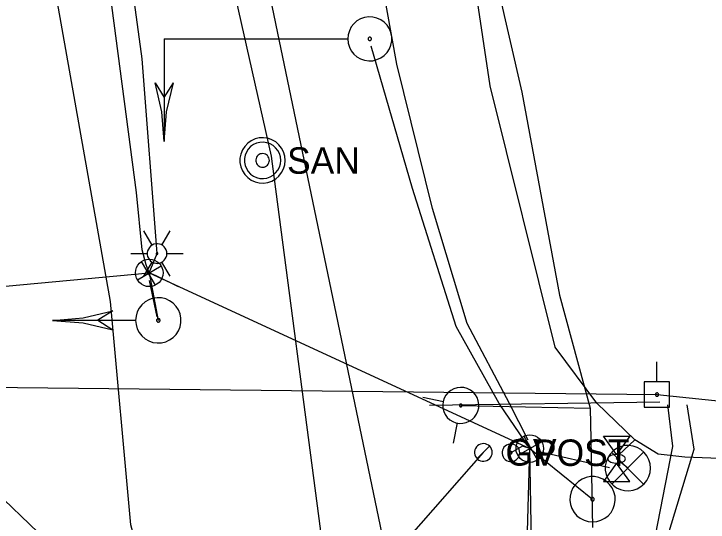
# Model space of a CAD drawing. Extents: x 600849 to 606371, y 330010 to 403088.
# Drawn here: x 605030.2 to 605131.2, y 338029.9 to 338103.8 of the extents above; entities that cross this region are included whole.
import ezdxf

# ---------------------------------------------------------------- set-up
doc = ezdxf.new("R2010")
doc.units = 0
for name, color, linetype in [('E_LTG', 7, 'Continuous'), ('E_LTG_CID', 7, 'Continuous'), ('E_MISCPROP', 7, 'Continuous'), ('E_SIG', 7, 'Continuous'), ('E_SIG_Conduit', 7, 'Continuous'), ('E_UTL_AG', 7, 'Continuous'), ('E_UTL_E_UG', 7, 'Continuous'), ('E_UTL_EPowerPole', 7, 'Continuous'), ('E_UTL_FO_UG', 7, 'Continuous'), ('E_UTL_G', 7, 'Continuous'), ('E_UTL_G_UG', 7, 'Continuous'), ('E_UTL_Loop_UG', 7, 'Continuous'), ('E_UTL_Overhead', 7, 'Continuous'), ('E_UTL_SAN', 7, 'Continuous'), ('E_UTL_SAN_UG', 7, 'Continuous'), ('E_UTL_TV_UG', 7, 'Continuous'), ('E_UTL_W_UG', 7, 'Continuous'), ('E_UTL_WHydrant', 7, 'Continuous')]:
    doc.layers.add(name, color=color, linetype=linetype)

# ---------------------------------------------------------------- blocks, each defined once
blk = doc.blocks.new('_U321')
at = {"layer": 'E_SIG'}
for p, q in [((0, 6.1), (0, -6.1)), ((-6.09, 0.4), (6.1, 0.4))]:
    blk.add_line(p, q, dxfattribs=at)
blk.add_circle((0, 0.01), 6.1, dxfattribs=at)
blk = doc.blocks.new('_U322')
at = {"layer": 'E_SIG'}
for p, q in [((0, 6.1), (0, -6.1)), ((-6.09, 0.4), (6.1, 0.4))]:
    blk.add_line(p, q, dxfattribs=at)
blk.add_circle((0, 0.01), 6.1, dxfattribs=at)

msp = doc.modelspace()

# ---------------------------------------------------------------- linework, layer by layer
at = {"layer": 'E_LTG'}
for points in [[(605050.29, 338070.16), (605049.09, 338072.22)], [(605051.71, 338070.16), (605052.91, 338072.22)], [(605052.43, 338068.92), (605052.4, 338069.19), (605052.33, 338069.45), (605052.2, 338069.7), (605052.03, 338069.91), (605051.83, 338070.09), (605051.59, 338070.22), (605051.34, 338070.31), (605051.07, 338070.35), (605050.8, 338070.34), (605050.53, 338070.27), (605050.29, 338070.16), (605050.06, 338070), (605049.88, 338069.81), (605049.73, 338069.58), (605049.63, 338069.33), (605049.58, 338069.06), (605049.58, 338068.79), (605049.63, 338068.52), (605049.73, 338068.27), (605049.88, 338068.04), (605050.06, 338067.84), (605050.29, 338067.69), (605050.53, 338067.57), (605050.8, 338067.51), (605051.07, 338067.5), (605051.34, 338067.54), (605051.59, 338067.62), (605051.83, 338067.76), (605052.03, 338067.94), (605052.2, 338068.15), (605052.33, 338068.39), (605052.4, 338068.65), (605052.43, 338068.92)], [(605052.43, 338068.92), (605052.4, 338069.19), (605052.33, 338069.45), (605052.2, 338069.7), (605052.03, 338069.91), (605051.83, 338070.09), (605051.59, 338070.22), (605051.34, 338070.31), (605051.07, 338070.35), (605050.8, 338070.34), (605050.53, 338070.27), (605050.29, 338070.16), (605050.06, 338070), (605049.88, 338069.81), (605049.73, 338069.58), (605049.63, 338069.33), (605049.58, 338069.06), (605049.58, 338068.79), (605049.63, 338068.52), (605049.73, 338068.27), (605049.88, 338068.04), (605050.06, 338067.84), (605050.29, 338067.69), (605050.53, 338067.57), (605050.8, 338067.51), (605051.07, 338067.5), (605051.34, 338067.54), (605051.59, 338067.62), (605051.83, 338067.76), (605052.03, 338067.94), (605052.2, 338068.15), (605052.33, 338068.39), (605052.4, 338068.65), (605052.43, 338068.92)], [(605052.43, 338068.92), (605052.4, 338069.19), (605052.33, 338069.45), (605052.2, 338069.7), (605052.03, 338069.91), (605051.83, 338070.09), (605051.59, 338070.22), (605051.34, 338070.31), (605051.07, 338070.35), (605050.8, 338070.34), (605050.53, 338070.27), (605050.29, 338070.16), (605050.06, 338070), (605049.88, 338069.81), (605049.73, 338069.58), (605049.63, 338069.33), (605049.58, 338069.06), (605049.58, 338068.79), (605049.63, 338068.52), (605049.73, 338068.27), (605049.88, 338068.04), (605050.06, 338067.84), (605050.29, 338067.69), (605050.53, 338067.57), (605050.8, 338067.51), (605051.07, 338067.5), (605051.34, 338067.54), (605051.59, 338067.62), (605051.83, 338067.76), (605052.03, 338067.94), (605052.2, 338068.15), (605052.33, 338068.39), (605052.4, 338068.65), (605052.43, 338068.92)], [(605047.19, 338068.92), (605049.57, 338068.92)], [(605051.12, 338068.92), (605051.12, 338068.95), (605051.11, 338068.97), (605051.1, 338068.99), (605051.09, 338069.01), (605051.07, 338069.02), (605051.05, 338069.03), (605051.03, 338069.04), (605051.01, 338069.04), (605050.98, 338069.04), (605050.96, 338069.04), (605050.94, 338069.03), (605050.92, 338069.01), (605050.91, 338069), (605050.89, 338068.98), (605050.89, 338068.96), (605050.88, 338068.94), (605050.88, 338068.91), (605050.89, 338068.89), (605050.89, 338068.87), (605050.91, 338068.85), (605050.92, 338068.83), (605050.94, 338068.82), (605050.96, 338068.81), (605050.98, 338068.81), (605051.01, 338068.8), (605051.03, 338068.81), (605051.05, 338068.82), (605051.07, 338068.83), (605051.09, 338068.84), (605051.1, 338068.86), (605051.11, 338068.88), (605051.12, 338068.9), (605051.12, 338068.92)], [(605052.43, 338068.92), (605054.81, 338068.92)], [(605049.09, 338065.62), (605050.29, 338067.69)], [(605052.91, 338065.62), (605051.71, 338067.69)]]:
    msp.add_lwpolyline(points, dxfattribs=at)
at = {"layer": 'E_LTG_CID'}
for points in [[(605051, 338068.92), (605048.82, 338097.26), (605044.44, 338129.66), (605035.18, 338175.44)], [(605049.87, 338066.12), (605051, 338068.92)]]:
    msp.add_lwpolyline(points, dxfattribs=at)
at = {"layer": 'E_MISCPROP'}
for points in [[(605103.75, 338039.96), (605103.73, 338040.21), (605103.66, 338040.44), (605103.55, 338040.66), (605103.4, 338040.85), (605103.21, 338041.01), (605103, 338041.13), (605102.77, 338041.21), (605102.53, 338041.25), (605102.29, 338041.23), (605102.05, 338041.18), (605101.83, 338041.08), (605101.63, 338040.93), (605101.46, 338040.76), (605101.33, 338040.55), (605101.24, 338040.33), (605101.19, 338040.09), (605101.19, 338039.84), (605101.24, 338039.6), (605101.33, 338039.38), (605101.46, 338039.17), (605101.63, 338038.99), (605101.83, 338038.85), (605102.05, 338038.75), (605102.29, 338038.69), (605102.53, 338038.68), (605102.77, 338038.72), (605103, 338038.8), (605103.21, 338038.92), (605103.4, 338039.08), (605103.55, 338039.27), (605103.66, 338039.49), (605103.73, 338039.72), (605103.75, 338039.96)], [(605102.63, 338039.96), (605102.63, 338039.99), (605102.62, 338040.02), (605102.6, 338040.05), (605102.59, 338040.07), (605102.56, 338040.09), (605102.54, 338040.11), (605102.51, 338040.12), (605102.48, 338040.12), (605102.45, 338040.12), (605102.42, 338040.12), (605102.39, 338040.1), (605102.36, 338040.09), (605102.34, 338040.06), (605102.33, 338040.04), (605102.32, 338040.01), (605102.31, 338039.98), (605102.31, 338039.95), (605102.32, 338039.92), (605102.33, 338039.89), (605102.34, 338039.86), (605102.36, 338039.84), (605102.39, 338039.82), (605102.42, 338039.81), (605102.45, 338039.81), (605102.48, 338039.8), (605102.51, 338039.81), (605102.54, 338039.82), (605102.56, 338039.83), (605102.59, 338039.85), (605102.6, 338039.88), (605102.62, 338039.9), (605102.63, 338039.93), (605102.63, 338039.96)]]:
    msp.add_lwpolyline(points, dxfattribs=at)
at = {"layer": 'E_SIG'}
for points in [[(605078.74, 338100.14), (605078.79, 338099.54), (605078.97, 338098.95), (605079.24, 338098.41), (605079.62, 338097.93), (605080.08, 338097.53), (605080.61, 338097.23), (605081.18, 338097.03), (605081.79, 338096.94), (605082.4, 338096.97), (605082.99, 338097.12), (605083.54, 338097.37), (605084.04, 338097.72), (605084.46, 338098.16), (605084.79, 338098.68), (605085.01, 338099.24), (605085.13, 338099.84), (605085.13, 338100.45), (605085.01, 338101.05), (605084.79, 338101.61), (605084.46, 338102.12), (605084.04, 338102.56), (605083.54, 338102.92), (605082.99, 338103.17), (605082.4, 338103.31), (605081.79, 338103.34), (605081.18, 338103.26), (605080.61, 338103.06), (605080.08, 338102.75), (605079.62, 338102.35), (605079.24, 338101.87), (605078.97, 338101.33), (605078.79, 338100.75), (605078.74, 338100.14)], [(605052.05, 338100.14), (605078.68, 338100.14)], [(605052.05, 338100.14), (605052.05, 338085.2)], [(605059.52, 338100.14), (605059.52, 338100.14)], [(605081.69, 338100.14), (605081.7, 338100.1), (605081.71, 338100.05), (605081.73, 338100.01), (605081.76, 338099.97), (605081.8, 338099.94), (605081.84, 338099.92), (605081.88, 338099.91), (605081.93, 338099.9), (605081.97, 338099.9), (605082.02, 338099.91), (605082.06, 338099.93), (605082.1, 338099.96), (605082.13, 338099.99), (605082.16, 338100.03), (605082.17, 338100.07), (605082.18, 338100.12), (605082.18, 338100.17), (605082.17, 338100.21), (605082.16, 338100.26), (605082.13, 338100.29), (605082.1, 338100.33), (605082.06, 338100.36), (605082.02, 338100.37), (605081.97, 338100.39), (605081.93, 338100.39), (605081.88, 338100.38), (605081.84, 338100.37), (605081.8, 338100.34), (605081.76, 338100.31), (605081.73, 338100.28), (605081.71, 338100.23), (605081.7, 338100.19), (605081.69, 338100.14)], [(605052.05, 338085.2), (605051.71, 338089.52), (605050.71, 338093.74)], [(605050.71, 338093.74), (605052.05, 338091.6)], [(605052.05, 338085.2), (605052.38, 338089.52), (605053.38, 338093.74)], [(605052.05, 338091.6), (605053.38, 338093.74)], [(605047.88, 338059.21), (605047.94, 338058.59), (605048.12, 338057.99), (605048.4, 338057.43), (605048.79, 338056.94), (605049.26, 338056.53), (605049.81, 338056.21), (605050.4, 338056.01), (605051.02, 338055.92), (605051.65, 338055.95), (605052.26, 338056.1), (605052.83, 338056.36), (605053.34, 338056.72), (605053.77, 338057.17), (605054.11, 338057.7), (605054.35, 338058.28), (605054.46, 338058.9), (605054.46, 338059.53), (605054.35, 338060.14), (605054.11, 338060.73), (605053.77, 338061.25), (605053.34, 338061.71), (605052.83, 338062.07), (605052.26, 338062.33), (605051.65, 338062.48), (605051.02, 338062.51), (605050.4, 338062.42), (605049.81, 338062.22), (605049.26, 338061.9), (605048.79, 338061.49), (605048.4, 338061), (605048.12, 338060.44), (605047.94, 338059.84), (605047.88, 338059.21)], [(605035.78, 338059.21), (605040.23, 338059.56), (605044.58, 338060.59)], [(605044.58, 338060.59), (605042.38, 338059.22)], [(605050.93, 338059.21), (605050.93, 338059.17), (605050.94, 338059.12), (605050.97, 338059.08), (605051, 338059.04), (605051.03, 338059.01), (605051.07, 338058.98), (605051.12, 338058.97), (605051.17, 338058.96), (605051.22, 338058.96), (605051.26, 338058.98), (605051.31, 338059), (605051.34, 338059.02), (605051.38, 338059.06), (605051.4, 338059.1), (605051.42, 338059.14), (605051.43, 338059.19), (605051.43, 338059.24), (605051.42, 338059.29), (605051.4, 338059.33), (605051.38, 338059.37), (605051.34, 338059.41), (605051.31, 338059.43), (605051.26, 338059.45), (605051.22, 338059.46), (605051.17, 338059.47), (605051.12, 338059.46), (605051.07, 338059.44), (605051.03, 338059.42), (605051, 338059.39), (605050.97, 338059.35), (605050.94, 338059.31), (605050.93, 338059.26), (605050.93, 338059.21)], [(605035.78, 338059.22), (605047.82, 338059.22)], [(605035.78, 338059.21), (605040.23, 338058.87), (605044.58, 338057.84)], [(605042.38, 338059.22), (605044.58, 338057.84)], [(605122.78, 338037.72), (605122.72, 338038.35), (605122.54, 338038.95), (605122.26, 338039.51), (605121.87, 338040), (605121.39, 338040.41), (605120.85, 338040.73), (605120.26, 338040.93), (605119.64, 338041.02), (605119.01, 338040.99), (605118.4, 338040.84), (605117.83, 338040.58), (605117.32, 338040.22), (605116.89, 338039.76), (605116.55, 338039.24), (605116.31, 338038.65), (605116.19, 338038.04), (605116.19, 338037.41), (605116.31, 338036.79), (605116.55, 338036.21), (605116.89, 338035.68), (605117.32, 338035.23), (605117.83, 338034.87), (605118.4, 338034.61), (605119.01, 338034.46), (605119.64, 338034.43), (605120.26, 338034.52), (605120.85, 338034.72), (605121.39, 338035.04), (605121.87, 338035.45), (605122.26, 338035.94), (605122.54, 338036.5), (605122.72, 338037.1), (605122.78, 338037.72)], [(605121.74, 338040.06), (605117.13, 338035.4)], [(605117.13, 338040.01), (605121.78, 338035.36)], [(605114.34, 338029.9), (605114.96, 338029.96), (605115.57, 338030.14), (605116.12, 338030.43), (605116.62, 338030.81), (605117.03, 338031.29), (605117.34, 338031.83), (605117.55, 338032.43), (605117.64, 338033.05), (605117.61, 338033.67), (605117.46, 338034.28), (605117.2, 338034.85), (605116.83, 338035.36), (605116.38, 338035.8), (605115.85, 338036.14), (605115.27, 338036.37), (605114.65, 338036.49), (605114.03, 338036.49), (605113.41, 338036.37), (605112.83, 338036.14), (605112.3, 338035.8), (605111.85, 338035.36), (605111.48, 338034.85), (605111.22, 338034.28), (605111.07, 338033.67), (605111.04, 338033.05), (605111.13, 338032.43), (605111.34, 338031.83), (605111.65, 338031.29), (605112.06, 338030.81), (605112.56, 338030.43), (605113.11, 338030.14), (605113.71, 338029.96), (605114.34, 338029.9)], [(605114.34, 338032.95), (605114.39, 338032.96), (605114.43, 338032.97), (605114.48, 338032.99), (605114.51, 338033.02), (605114.54, 338033.06), (605114.57, 338033.1), (605114.58, 338033.14), (605114.59, 338033.19), (605114.59, 338033.24), (605114.58, 338033.29), (605114.56, 338033.33), (605114.53, 338033.37), (605114.5, 338033.4), (605114.45, 338033.43), (605114.41, 338033.45), (605114.36, 338033.45), (605114.32, 338033.45), (605114.27, 338033.45), (605114.22, 338033.43), (605114.18, 338033.4), (605114.15, 338033.37), (605114.12, 338033.33), (605114.1, 338033.29), (605114.09, 338033.24), (605114.09, 338033.19), (605114.09, 338033.14), (605114.11, 338033.1), (605114.13, 338033.06), (605114.17, 338033.02), (605114.2, 338032.99), (605114.25, 338032.97), (605114.29, 338032.96), (605114.34, 338032.95)]]:
    msp.add_lwpolyline(points, dxfattribs=at)
at = {"layer": 'E_SIG_Conduit'}
for points in [[(605049.87, 338066.12), (605049.43, 338067.28), (605048.84, 338069.45), (605047.99, 338077.82), (605044.16, 338106.9), (605044.15, 338107.5)], [(604986.64, 338059.22), (604991.82, 338060.74), (605049.87, 338066.12), (605105.21, 338040.56)], [(605054.12, 338064.11), (605050.87, 338065.67), (605049.87, 338066.12)], [(605049.87, 338066.12), (605051.18, 338059.21)], [(605049.87, 338065), (605050.97, 338059.72)], [(605105.21, 338040.56), (605104.15, 338040.93), (605102.47, 338039.96)], [(605103.44, 337976.83), (605105.21, 338040.56)]]:
    msp.add_lwpolyline(points, dxfattribs=at)
at = {"layer": 'E_UTL_AG'}
for points in [[(605115.94, 338042.38), (605119.76, 338042.38)], [(605117.85, 338039.72), (605115.94, 338042.38)], [(605119.76, 338042.38), (605117.85, 338039.72)], [(605119.12, 338039.08), (605119.1, 338039.2), (605119.03, 338039.32), (605118.92, 338039.43), (605118.77, 338039.52), (605118.59, 338039.6), (605118.38, 338039.66), (605118.15, 338039.7), (605117.91, 338039.72), (605117.67, 338039.71), (605117.43, 338039.68), (605117.21, 338039.63), (605117.02, 338039.56), (605116.85, 338039.48), (605116.72, 338039.37), (605116.63, 338039.26), (605116.59, 338039.14), (605116.59, 338039.02), (605116.63, 338038.9), (605116.72, 338038.79), (605116.85, 338038.69), (605117.02, 338038.6), (605117.21, 338038.53), (605117.43, 338038.48), (605117.67, 338038.46), (605117.91, 338038.45), (605118.15, 338038.47), (605118.38, 338038.51), (605118.59, 338038.57), (605118.77, 338038.65), (605118.92, 338038.74), (605119.03, 338038.85), (605119.1, 338038.96), (605119.12, 338039.08)], [(605117.85, 338038.45), (605115.94, 338035.78)], [(605119.76, 338035.78), (605117.85, 338038.45)], [(605115.94, 338035.78), (605119.76, 338035.78)]]:
    msp.add_lwpolyline(points, dxfattribs=at)
at = {"layer": 'E_UTL_E_UG'}
for points in [[(605213.1, 338038.79), (605193.26, 338037.99), (605160.59, 338038.08), (605127.76, 338039.3), (605123.89, 338039.74), (605120.48, 338041.84), (605114.99, 338047.19), (605108.92, 338055.3), (605099.44, 338093.33), (605096.13, 338115.73), (605086.65, 338141.8)], [(605061.54, 337888.91), (605059.04, 337917.06), (605057.57, 337942.06), (605056.67, 337966.94), (605055.22, 337996.91), (605055.37, 338007.21), (605054.55, 338009.74), (605050.03, 338019.17), (605047.17, 338029.49), (605044.23, 338061.96), (605036.53, 338105.43), (605031.55, 338127.51)], [(605105.21, 338040.56), (605100.75, 338047.14), (605094.5, 338058.34), (605088.14, 338078.4), (605082.12, 338099.1)], [(605090.63, 338046.89), (605124.15, 338047.38)], [(605119.48, 338037.72), (605117.85, 338039.08), (605118.15, 338039.68), (605120.48, 338041.84)], [(605105.21, 338040.56), (605114.34, 338033.2)], [(605106.18, 338040.24), (605116.81, 338037.82)]]:
    msp.add_lwpolyline(points, dxfattribs=at)
at = {"layer": 'E_UTL_EPowerPole'}
for points in [[(605123.69, 338050.26), (605123.69, 338053.17)], [(605125.53, 338050.26), (605121.85, 338050.26)], [(605121.85, 338050.26), (605121.85, 338046.57)], [(605125.53, 338046.57), (605125.53, 338050.26)], [(605123.96, 338048.42), (605123.95, 338048.46), (605123.94, 338048.51), (605123.92, 338048.55), (605123.89, 338048.58), (605123.86, 338048.61), (605123.82, 338048.63), (605123.78, 338048.65), (605123.73, 338048.65), (605123.69, 338048.65), (605123.64, 338048.64), (605123.6, 338048.62), (605123.56, 338048.6), (605123.53, 338048.56), (605123.51, 338048.53), (605123.49, 338048.48), (605123.48, 338048.44), (605123.48, 338048.39), (605123.49, 338048.35), (605123.51, 338048.31), (605123.53, 338048.27), (605123.56, 338048.24), (605123.6, 338048.21), (605123.64, 338048.19), (605123.69, 338048.18), (605123.73, 338048.18), (605123.78, 338048.19), (605123.82, 338048.2), (605123.86, 338048.22), (605123.89, 338048.25), (605123.92, 338048.29), (605123.94, 338048.33), (605123.95, 338048.37), (605123.96, 338048.42)], [(605121.85, 338046.57), (605125.53, 338046.57)]]:
    msp.add_lwpolyline(points, dxfattribs=at)
at = {"layer": 'E_UTL_FO_UG'}
msp.add_lwpolyline([(605104.97, 338041.81), (605102.26, 338047.12), (605096.12, 338058.75), (605091.05, 338075.5), (605085.86, 338096.48), (605078.31, 338138.32), (605071.34, 338178.54)], dxfattribs=at)
at = {"layer": 'E_UTL_G'}
for points in [[(605099.74, 338040.01), (605099.72, 338040.26), (605099.65, 338040.49), (605099.54, 338040.71), (605099.39, 338040.9), (605099.2, 338041.06), (605098.99, 338041.18), (605098.76, 338041.26), (605098.52, 338041.3), (605098.28, 338041.28), (605098.04, 338041.23), (605097.82, 338041.13), (605097.62, 338040.98), (605097.45, 338040.81), (605097.32, 338040.6), (605097.23, 338040.38), (605097.18, 338040.14), (605097.18, 338039.89), (605097.23, 338039.65), (605097.32, 338039.43), (605097.45, 338039.22), (605097.62, 338039.04), (605097.82, 338038.9), (605098.04, 338038.8), (605098.28, 338038.74), (605098.52, 338038.73), (605098.76, 338038.77), (605098.99, 338038.85), (605099.2, 338038.97), (605099.39, 338039.13), (605099.54, 338039.32), (605099.65, 338039.54), (605099.72, 338039.77), (605099.74, 338040.01)], [(605097.55, 338039.11), (605099.37, 338040.92)]]:
    msp.add_lwpolyline(points, dxfattribs=at)
at = {"layer": 'E_UTL_G_UG'}
for points in [[(605086.15, 338016.47), (605063.85, 338123.62)], [(605087.65, 338027.67), (605098.46, 338040.01)]]:
    msp.add_lwpolyline(points, dxfattribs=at)
at = {"layer": 'E_UTL_Loop_UG'}
msp.add_lwpolyline([(605105.53, 338024.12), (605105.21, 338040.56)], dxfattribs=at)
at = {"layer": 'E_UTL_Overhead'}
msp.add_lwpolyline([(604103.07, 338065.18), (604129.71, 338064.26), (604267.8, 338061.89), (604345.51, 338120), (604559.22, 338082.12), (604693.82, 338059.02), (604714.84, 338054.01), (604784.9, 338053.56), (604829.08, 338053.72), (604872.92, 338052.19), (604977.47, 338050.01), (605123.72, 338048.42), (605215.39, 338038.9)], dxfattribs=at)
at = {"layer": 'E_UTL_SAN'}
for points in [[(605069.64, 338082.47), (605069.58, 338083.1), (605069.41, 338083.7), (605069.12, 338084.26), (605068.73, 338084.75), (605068.26, 338085.16), (605067.71, 338085.48), (605067.12, 338085.68), (605066.5, 338085.77), (605065.87, 338085.74), (605065.26, 338085.59), (605064.69, 338085.33), (605064.18, 338084.97), (605063.75, 338084.51), (605063.41, 338083.99), (605063.18, 338083.4), (605063.06, 338082.79), (605063.06, 338082.16), (605063.18, 338081.55), (605063.41, 338080.96), (605063.75, 338080.44), (605064.18, 338079.98), (605064.69, 338079.62), (605065.26, 338079.36), (605065.87, 338079.21), (605066.5, 338079.18), (605067.12, 338079.27), (605067.71, 338079.47), (605068.26, 338079.79), (605068.73, 338080.2), (605069.12, 338080.69), (605069.41, 338081.25), (605069.58, 338081.85), (605069.64, 338082.47)], [(605068.98, 338082.47), (605068.93, 338082.97), (605068.79, 338083.46), (605068.56, 338083.9), (605068.25, 338084.3), (605067.87, 338084.63), (605067.44, 338084.88), (605066.96, 338085.04), (605066.47, 338085.11), (605065.97, 338085.09), (605065.48, 338084.97), (605065.02, 338084.76), (605064.61, 338084.47), (605064.27, 338084.11), (605064, 338083.68), (605063.81, 338083.22), (605063.71, 338082.73), (605063.71, 338082.22), (605063.81, 338081.73), (605064, 338081.27), (605064.27, 338080.84), (605064.61, 338080.48), (605065.02, 338080.19), (605065.48, 338079.98), (605065.97, 338079.86), (605066.47, 338079.84), (605066.96, 338079.91), (605067.44, 338080.07), (605067.87, 338080.32), (605068.25, 338080.65), (605068.56, 338081.05), (605068.79, 338081.49), (605068.93, 338081.98), (605068.98, 338082.47)], [(605067.33, 338082.47), (605067.31, 338082.66), (605067.26, 338082.84), (605067.17, 338083.01), (605067.06, 338083.16), (605066.92, 338083.28), (605066.75, 338083.38), (605066.57, 338083.44), (605066.39, 338083.46), (605066.2, 338083.45), (605066.02, 338083.41), (605065.85, 338083.33), (605065.69, 338083.22), (605065.56, 338083.09), (605065.46, 338082.93), (605065.39, 338082.75), (605065.36, 338082.57), (605065.36, 338082.38), (605065.39, 338082.2), (605065.46, 338082.02), (605065.56, 338081.86), (605065.69, 338081.73), (605065.85, 338081.62), (605066.02, 338081.54), (605066.2, 338081.5), (605066.39, 338081.49), (605066.57, 338081.51), (605066.75, 338081.57), (605066.92, 338081.67), (605067.06, 338081.79), (605067.17, 338081.94), (605067.26, 338082.11), (605067.31, 338082.29), (605067.33, 338082.47)]]:
    msp.add_lwpolyline(points, dxfattribs=at)
at = {"layer": 'E_UTL_SAN_UG'}
for p, q in [((605067.64, 338083.08), (604998.36, 338390.82)), ((605080.42, 337985.92), (605067.64, 338083.08))]:
    msp.add_line(p, q, dxfattribs=at)
at = {"layer": 'E_UTL_TV_UG'}
for points in [[(605108.19, 337942.8), (605108.43, 337954.92), (605110.98, 337973.85), (605116.8, 337998.64), (605123.14, 338026.19), (605126.02, 338040.87), (605126, 338040.9), (605125.28, 338046.95)], [(605110.21, 337942.94), (605110.1, 337955.25), (605112.87, 337973.35), (605118.22, 337998.07), (605124.68, 338025.8), (605129.14, 338040.47), (605128.12, 338046.92)]]:
    msp.add_lwpolyline(points, dxfattribs=at)
at = {"layer": 'E_UTL_W_UG'}
for points in [[(605092.03, 338144.65), (605104.07, 338092.4), (605109.53, 338062.87), (605114.02, 338046.46), (605114.08, 338041.92), (605114.33, 338029.1)], [(604994.97, 338065.55), (605042.42, 338019.97)], [(605095.18, 338046.84), (605114.02, 338046.46)]]:
    msp.add_lwpolyline(points, dxfattribs=at)
at = {"layer": 'E_UTL_WHydrant'}
for points in [[(605093.73, 338049.03), (605093.34, 338048.72), (605093.02, 338048.34), (605092.78, 338047.9), (605092.62, 338047.43), (605092.56, 338046.93), (605092.59, 338046.44), (605092.71, 338045.95), (605092.93, 338045.5), (605093.22, 338045.1), (605093.59, 338044.76), (605094.01, 338044.5), (605094.48, 338044.32), (605094.97, 338044.23), (605095.46, 338044.24), (605095.95, 338044.34), (605096.41, 338044.53), (605096.83, 338044.8), (605097.19, 338045.15), (605097.47, 338045.56), (605097.67, 338046.02), (605097.78, 338046.51), (605097.8, 338047), (605097.72, 338047.5), (605097.55, 338047.97), (605097.3, 338048.39), (605096.96, 338048.77), (605096.57, 338049.07), (605096.12, 338049.29), (605095.64, 338049.43), (605095.14, 338049.47), (605094.65, 338049.41), (605094.17, 338049.27), (605093.73, 338049.03)], [(605092.64, 338047.36), (605089.67, 338047.97)], [(605095.07, 338047.01), (605095.04, 338046.99), (605095.01, 338046.96), (605095, 338046.92), (605094.98, 338046.89), (605094.98, 338046.85), (605094.98, 338046.81), (605094.99, 338046.78), (605095.01, 338046.74), (605095.03, 338046.71), (605095.06, 338046.68), (605095.09, 338046.66), (605095.13, 338046.65), (605095.16, 338046.64), (605095.2, 338046.64), (605095.24, 338046.65), (605095.27, 338046.67), (605095.31, 338046.69), (605095.33, 338046.71), (605095.35, 338046.75), (605095.37, 338046.78), (605095.38, 338046.82), (605095.38, 338046.86), (605095.37, 338046.89), (605095.36, 338046.93), (605095.34, 338046.96), (605095.32, 338046.99), (605095.29, 338047.01), (605095.25, 338047.03), (605095.22, 338047.04), (605095.18, 338047.04), (605095.14, 338047.04), (605095.1, 338047.03), (605095.07, 338047.01)], [(605094.66, 338044.3), (605094.06, 338041.33)]]:
    msp.add_lwpolyline(points, dxfattribs=at)

# ---------------------------------------------------------------- block references
at = {"layer": 'E_SIG_Conduit', "xscale": 0.32808333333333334, "yscale": 0.32808333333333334}
for name, p, rotation in [('_U321', (605049.87, 338066.12), 120.03254714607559), ('_U322', (605105.21, 338040.56), -60.197503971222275)]:
    msp.add_blockref(name, p, dxfattribs=dict(at, rotation=rotation))

# ---------------------------------------------------------------- texts
at = {"layer": 'E_MISCPROP'}
msp.add_text('POST', height=3.85, dxfattribs=at).set_placement((605105.68, 338038.04))
at = {"layer": 'E_UTL_G'}
msp.add_text('GV', height=3.85, dxfattribs=at).set_placement((605101.67, 338038.09))
at = {"layer": 'E_UTL_SAN'}
msp.add_text('SAN', height=3.849, dxfattribs=at).set_placement((605069.91, 338080.53))

doc.saveas('drawing.dxf')
